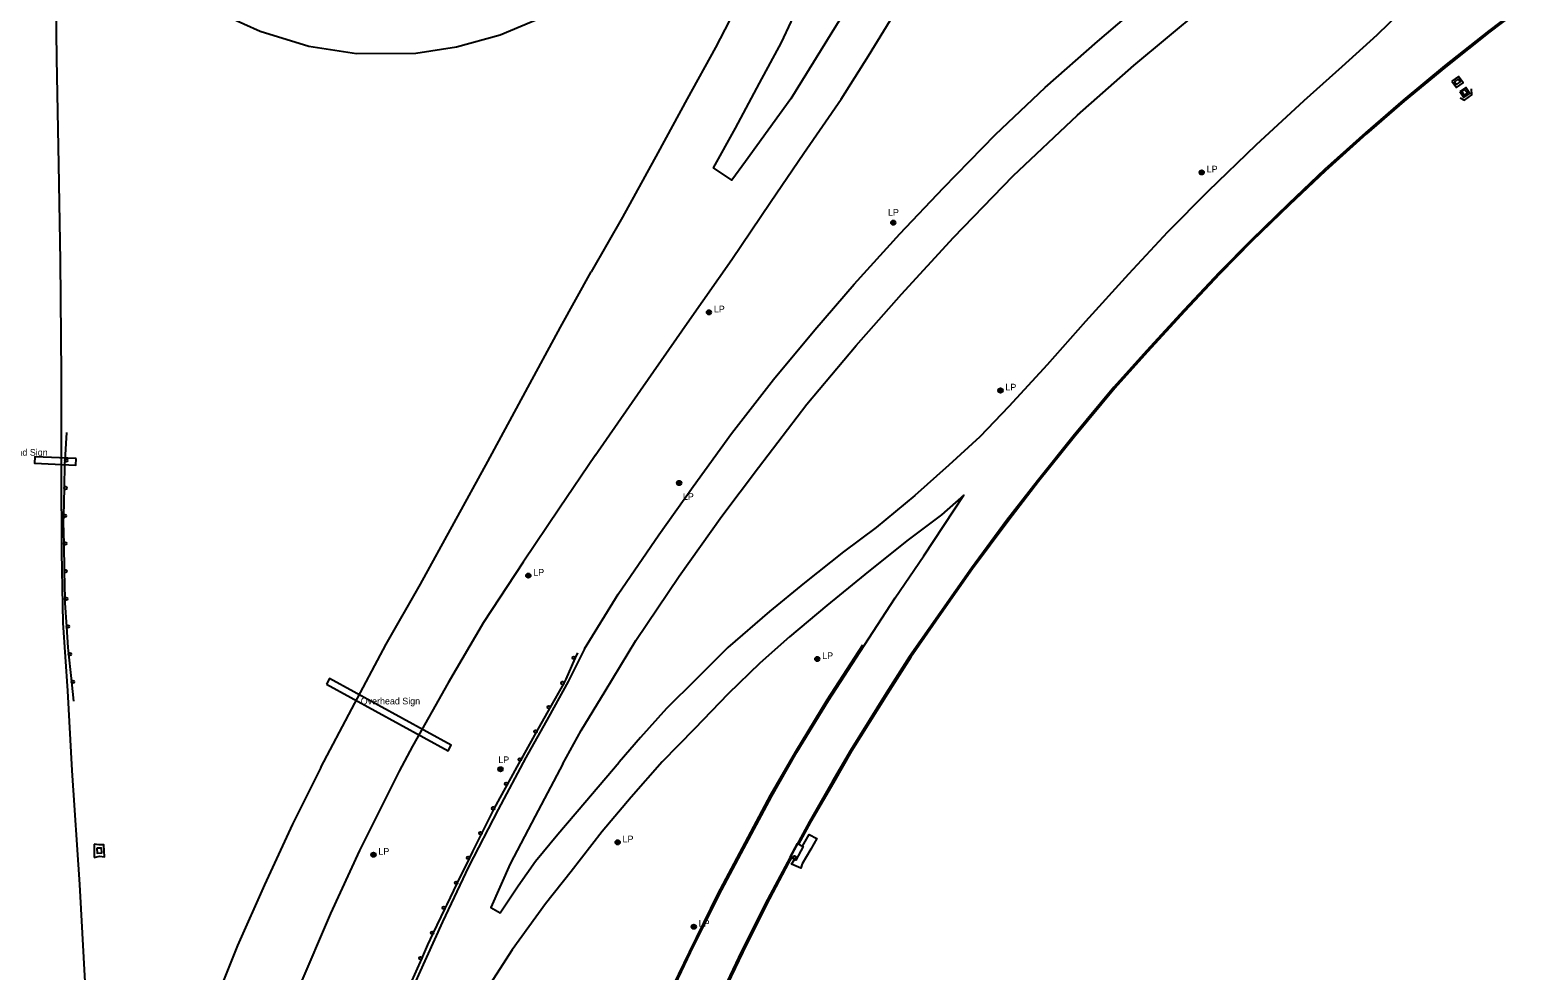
# Model space of a CAD drawing. Extents: x 2402803 to 2427059, y 6985292 to 6997652.
# Drawn here: x 2410720 to 2411807, y 6990282 to 6990960 of the extents above; entities that cross this region are included whole.
import ezdxf

# ---------------------------------------------------------------- set-up
doc = ezdxf.new("R2010")
doc.units = 0
for name, color, linetype in [('p_drainage conc drain', 7, 'Continuous'), ('p_dtm retaining wall', 7, 'Continuous'), ('p_road - paved curb', 7, 'Continuous'), ('p_road bridge end', 7, 'Continuous'), ('p_road guard rails', 7, 'Continuous'), ('p_structure general', 7, 'Continuous'), ('p_structure slab', 7, 'Continuous'), ('p_utility manhole', 7, 'Continuous')]:
    doc.layers.add(name, color=color, linetype=linetype)

msp = doc.modelspace()

# ---------------------------------------------------------------- linework, layer by layer
at = {"layer": 'p_drainage conc drain'}
for points in [[(2411276.6, 6990371.5), (2411281.4, 6990380), (2411287.1, 6990377), (2411282.8, 6990369.4), (2411276.5, 6990358.8), (2411275.4, 6990355.6), (2411268.8, 6990358.6), (2411270.8, 6990362)], [(2410766, 6990373), (2410766.1, 6990363.5)], [(2410766.1, 6990363.5), (2410770, 6990364.3), (2410773.4, 6990363.8), (2410772.9, 6990372.6), (2410769.4, 6990372.6), (2410766, 6990373)]]:
    msp.add_lwpolyline(points, dxfattribs=at)
at = {"layer": 'p_dtm retaining wall'}
msp.add_lwpolyline([(2411750.9, 6990910.7), (2411753.8, 6990909.1), (2411759.3, 6990913), (2411758.9, 6990917.3)], dxfattribs=at)
at = {"layer": 'p_road - paved curb'}
for points in [[(2411292.7, 6991404.7), (2411296.3, 6991381.2), (2411299.6, 6991355.2), (2411302.1, 6991327.9), (2411303.6, 6991291.7), (2411302.4, 6991262.3), (2411300.1, 6991232.3), (2411296.8, 6991200.2), (2411290.6, 6991161.4), (2411283.1, 6991122.4), (2411270.8, 6991077.6), (2411256.2, 6991035.2), (2411231, 6990979.9), (2411213.9, 6990947.1), (2411193.6, 6990910), (2411172.4, 6990871.2), (2411146.8, 6990824.7), (2411124.3, 6990785.3)], [(2410750.2, 6990426.2), (2410747.1, 6990483.4), (2410743.8, 6990532.5), (2410742.8, 6990583.3), (2410742.5, 6990642.4), (2410742.4, 6990711.5), (2410741.7, 6990793.4), (2410740.5, 6990862.7), (2410739.1, 6990939.1), (2410738.5, 6990996.2)], [(2411323.5, 6990999.6), (2411297.7, 6990957.8), (2411268.2, 6990910.1), (2411235.5, 6990864.8), (2411225.8, 6990851.5), (2411212.5, 6990860.3), (2411228.4, 6990888.9), (2411245.7, 6990921.3), (2411261.6, 6990950.6), (2411275.5, 6990980.3)], [(2411806.2, 6990985.6), (2411771.4, 6990959.1), (2411739.4, 6990933.7), (2411709.7, 6990909.1), (2411682.5, 6990885.5), (2411653, 6990859), (2411627.1, 6990834.4), (2411600, 6990808.1), (2411576.9, 6990784.6), (2411551.5, 6990757.8), (2411524.6, 6990728.4), (2411501, 6990702.2), (2411471.8, 6990667), (2411446, 6990634.9), (2411423.8, 6990606.1), (2411398.4, 6990571.9), (2411375.9, 6990539.7), (2411353.9, 6990508.2), (2411337.1, 6990481.9), (2411311.2, 6990440.4)], [(2411806.8, 6990984.8), (2411772.1, 6990958.3), (2411740.1, 6990932.9), (2411710.3, 6990908.3), (2411683.2, 6990884.8), (2411653.6, 6990858.2), (2411627.8, 6990833.7), (2411600.7, 6990807.4), (2411577.6, 6990783.9), (2411552.2, 6990757.1), (2411525.3, 6990727.7), (2411501.8, 6990701.6), (2411472.6, 6990666.3), (2411446.8, 6990634.3), (2411424.6, 6990605.5), (2411399.2, 6990571.3), (2411376.7, 6990539.1), (2411354.8, 6990507.7), (2411338, 6990481.4), (2411312.1, 6990439.9)], [(2411119.6, 6990513.7), (2411143.8, 6990553.1), (2411173.2, 6990596), (2411197.9, 6990630.7), (2411225.6, 6990668.9), (2411255.7, 6990707.9), (2411285.5, 6990743.6), (2411313.9, 6990776.5), (2411346.9, 6990812.8), (2411378.3, 6990846), (2411415.7, 6990884.4), (2411451.6, 6990918.1), (2411489.3, 6990951.3), (2411525.1, 6990982.2)], [(2411127.2, 6990653.1), (2411159.9, 6990700.1), (2411195.2, 6990750.9), (2411225.7, 6990794.3), (2411253.5, 6990835.7), (2411277.6, 6990871), (2411304.6, 6990909.8), (2411324.2, 6990941), (2411346.3, 6990977)], [(2411134.5, 6990483.2), (2411156.6, 6990519.8), (2411187.8, 6990566.1), (2411218.5, 6990609.4), (2411245, 6990644.3), (2411279.9, 6990690.1), (2411315.4, 6990732.4), (2411348.1, 6990769.3), (2411385.5, 6990810.2), (2411428.5, 6990854.5), (2411474.9, 6990898.2), (2411515.5, 6990934.1), (2411564.1, 6990974.5)], [(2411716.4, 6990981), (2411690.7, 6990956), (2411665.4, 6990933), (2411638, 6990908.5), (2411603.4, 6990876.7), (2411569, 6990843.6), (2411539.9, 6990814), (2411511.6, 6990783.6), (2411480.7, 6990749.6), (2411453, 6990718.4), (2411425.3, 6990688.3), (2411404.4, 6990666.6), (2411382.1, 6990646.1), (2411357.6, 6990624.2), (2411329.7, 6990601.1), (2411306.3, 6990583.6), (2411278.2, 6990561.3), (2411252.9, 6990540.6), (2411222.9, 6990514.6), (2411200.1, 6990491.8), (2411178.7, 6990470.8), (2411160, 6990449.8), (2411144.5, 6990432.2)], [(2410862.2, 6990969.3), (2410885.7, 6990958.8), (2410920.9, 6990947.9), (2410955.1, 6990942.6), (2410997.9, 6990942.9), (2411027.2, 6990947.4), (2411058.7, 6990956.2), (2411088.5, 6990968.6)], [(2410929.5, 6990428.2), (2410951.9, 6990470.5), (2410976.5, 6990517.1), (2411001.2, 6990560.4), (2411025.5, 6990604.5), (2411049.8, 6990648.7), (2411077, 6990698.9), (2411102.2, 6990745.6), (2411124.3, 6990785.3)], [(2411127.2, 6990653.1), (2411101.4, 6990615.2), (2411075.3, 6990576.3), (2411046.7, 6990532.6), (2411021.3, 6990489.3), (2410995.5, 6990443.5), (2410986, 6990425.7)], [(2411321.1, 6990516.1), (2411343.5, 6990550.4), (2411364.2, 6990580.7), (2411392.9, 6990624.4), (2411376.8, 6990610.4), (2411351.9, 6990591.5), (2411321.6, 6990567.4), (2411294.1, 6990545), (2411267.3, 6990522.5), (2411245.9, 6990503.5), (2411223.1, 6990481.4), (2411198.9, 6990456.2), (2411175.5, 6990432.4)], [(2411119.6, 6990513.7), (2411107.7, 6990490.2), (2411093.6, 6990464.5), (2411077.2, 6990435.4)], [(2411271.9, 6990439.8), (2411294.4, 6990477), (2411320.2, 6990516.7)], [(2411272.7, 6990439.3), (2411295.3, 6990476.5), (2411321.1, 6990516.1)], [(2411104, 6990431), (2411117, 6990454.8), (2411134.5, 6990483.2)], [(2411077.2, 6990435.4), (2411057.3, 6990398.1), (2411035.8, 6990356.7), (2411017.1, 6990317.1), (2410999.9, 6990278.9), (2410983.4, 6990241.6), (2410965.2, 6990196.4), (2410949.7, 6990154), (2410931.2, 6990099.7), (2410915.5, 6990049.2), (2410901.9, 6990001.9), (2410888.9, 6989953.2), (2410879.3, 6989910), (2410868.1, 6989857.3), (2410860.6, 6989809.8), (2410850.7, 6989745.5), (2410845.4, 6989691.3), (2410843.9, 6989676.2)], [(2411175.5, 6990432.4), (2411153.1, 6990406.8), (2411132.3, 6990382.1), (2411109.8, 6990353.4), (2411091.4, 6990329.9), (2411067.4, 6990296.9), (2411044.9, 6990261.8), (2411028, 6990236), (2411013.1, 6990206.7), (2410990.6, 6990163), (2410969.3, 6990114.8), (2410949.6, 6990066.5), (2410933.3, 6990021), (2410918.6, 6989972.7), (2410906.2, 6989919.8), (2410894.1, 6989861.8), (2410886.5, 6989819.5), (2410876.9, 6989763.5), (2410873, 6989734.9), (2410867.2, 6989682.7), (2410866.8, 6989677.5)], [(2411104, 6990431), (2411083.9, 6990393.1), (2411065.9, 6990358.9), (2411052, 6990327.4), (2411058.7, 6990323.5), (2411071.8, 6990343.1), (2411084.3, 6990360.8), (2411100.2, 6990380.2), (2411119.8, 6990403.1), (2411144.5, 6990432.2)], [(2411055.6, 6989902.9), (2411061.7, 6989926.2), (2411068.4, 6989953.3), (2411077.7, 6989986.1), (2411086.7, 6990017), (2411097.2, 6990050.2), (2411106.7, 6990079.9), (2411118.3, 6990111.9), (2411130.8, 6990146.1), (2411146.2, 6990184.9), (2411163.4, 6990226), (2411179.6, 6990263), (2411195.1, 6990295.3), (2411215.6, 6990337), (2411233.4, 6990370.4), (2411253.6, 6990408.2), (2411271.9, 6990439.8)], [(2411056.5, 6989902.6), (2411062.7, 6989925.9), (2411069.4, 6989953.1), (2411078.7, 6989985.8), (2411087.7, 6990016.8), (2411098.1, 6990049.9), (2411107.7, 6990079.6), (2411119.2, 6990111.6), (2411131.7, 6990145.8), (2411147.1, 6990184.5), (2411164.4, 6990225.6), (2411180.5, 6990262.5), (2411196, 6990294.9), (2411216.5, 6990336.6), (2411234.3, 6990369.9), (2411254.5, 6990407.7), (2411272.7, 6990439.3)], [(2411311.2, 6990440.4), (2411298.1, 6990417.8), (2411281.6, 6990389.3), (2411265.8, 6990360.1), (2411249.8, 6990330), (2411232.8, 6990295.8), (2411215.9, 6990260.4)], [(2411312.1, 6990439.9), (2411299, 6990417.3), (2411282.5, 6990388.9), (2411273.9, 6990373)], [(2410929.5, 6990428.2), (2410909.1, 6990387.5), (2410888.8, 6990343.6), (2410869.3, 6990300), (2410848.5, 6990247.8), (2410831.5, 6990202.2), (2410816.7, 6990156.7), (2410801.9, 6990109.4), (2410784.9, 6990050.6), (2410774.9, 6990010.3), (2410767.1, 6989980.5), (2410762.1, 6989982), (2410763.1, 6990047.1), (2410762.3, 6990116.3), (2410761.8, 6990192.5), (2410759.6, 6990273.9), (2410755.8, 6990343.9), (2410750.2, 6990426.2)], [(2410986, 6990425.7), (2410957.4, 6990368.4), (2410936.4, 6990323), (2410913.6, 6990269.7), (2410894.9, 6990223.2), (2410875, 6990171.1), (2410860, 6990123.7), (2410841.8, 6990060.8), (2410824.8, 6989993.5), (2410812.6, 6989945.6), (2410800, 6989885.2), (2410789.9, 6989823.8), (2410780.5, 6989751.8), (2410774.9, 6989685.5)], [(2411268.5, 6990363), (2411266.6, 6990359.6), (2411250.7, 6990329.5), (2411233.7, 6990295.3), (2411216.8, 6990260), (2411202.3, 6990227.4), (2411182.4, 6990181.6), (2411167, 6990142.5), (2411157.1, 6990116.7)]]:
    msp.add_lwpolyline(points, dxfattribs=at)
at = {"layer": 'p_road bridge end'}
for points in [[(2410767.9, 6990370.1), (2410768.1, 6990366.5), (2410771.5, 6990366.7), (2410771.3, 6990370.2)], [(2411267.8, 6990363.6), (2411273.1, 6990373.4), (2411277.1, 6990371.3), (2411271.8, 6990361.5)]]:
    msp.add_lwpolyline(points, close=True, dxfattribs=at)
at = {"layer": 'p_road guard rails'}
for p, q in [((2410746, 6990669.5), (2410744.8, 6990649.6)), ((2410744.3, 6990629.6), (2410743.9, 6990609.6)), ((2410744.1, 6990589.6), (2410744.5, 6990569.7)), ((2410744.5, 6990569.7), (2410744.9, 6990549.7)), ((2411112.9, 6990506.8), (2411114.6, 6990510.9)), ((2410749.6, 6990489.9), (2410751.2, 6990476.1)), ((2411094.7, 6990471.2), (2411104.5, 6990488.6)), ((2411085, 6990453.7), (2411094.7, 6990471.2)), ((2411075.2, 6990436.3), (2411085, 6990453.7)), ((2411064, 6990416), (2411073.7, 6990433.5)), ((2411073.7, 6990433.5), (2411075.2, 6990436.3)), ((2411045.5, 6990380.6), (2411054.5, 6990398.4)), ((2411027.8, 6990344.7), (2411036.5, 6990362.7)), ((2411010.5, 6990308.7), (2411019.1, 6990326.7)), ((2410994.2, 6990272.2), (2411002.2, 6990290.5))]:
    msp.add_line(p, q, dxfattribs=at)
for points in [[(2410744.8, 6990649.6), (2410744.7, 6990647.4), (2410744.3, 6990629.6)], [(2410743.9, 6990609.6), (2410743.8, 6990604.9), (2410744.1, 6990589.6)], [(2410744.9, 6990549.7), (2410745, 6990547), (2410746.1, 6990529.7)], [(2410746.1, 6990529.7), (2410747, 6990514.6), (2410747.5, 6990509.8)], [(2410747.5, 6990509.8), (2410749.1, 6990494.5), (2410749.6, 6990489.9)], [(2411104.5, 6990488.6), (2411106.4, 6990492), (2411112.9, 6990506.8)], [(2411054.5, 6990398.4), (2411057.3, 6990403.8), (2411064, 6990416)], [(2411036.5, 6990362.7), (2411039, 6990367.8), (2411045.5, 6990380.6)], [(2411019.1, 6990326.7), (2411020.5, 6990329.5), (2411027.8, 6990344.7)], [(2411002.2, 6990290.5), (2411006.6, 6990300.5), (2411010.5, 6990308.7)]]:
    msp.add_lwpolyline(points, dxfattribs=at)
for centre in [(2410745.8, 6990649.5), (2410745.3, 6990629.6), (2410744.9, 6990609.6), (2410745.1, 6990589.7), (2410745.5, 6990569.7), (2410745.9, 6990549.7), (2410747.1, 6990529.8), (2410748.5, 6990509.9), (2411111.9, 6990507.2), (2410750.6, 6990490), (2411103.6, 6990489.1), (2411093.9, 6990471.7), (2411084.1, 6990454.2), (2411072.8, 6990434), (2411063.1, 6990416.5), (2411053.6, 6990398.8), (2411044.6, 6990381), (2411035.6, 6990363.1), (2411026.9, 6990345.2), (2411018.2, 6990327.2), (2411009.6, 6990309.1), (2411001.3, 6990290.9)]:
    msp.add_circle(centre, 1, dxfattribs=at)
at = {"layer": 'p_structure general'}
for points in [[(2411746.8, 6990922.2), (2411749.5, 6990924.1), (2411750.7, 6990922.3), (2411748, 6990920.4)], [(2411752, 6990915.2), (2411754.2, 6990916.7), (2411756, 6990914.3), (2411753.7, 6990912.7)], [(2410753, 6990650.8), (2410723.2, 6990652.2), (2410723, 6990647.5), (2410752.8, 6990646.1)], [(2410933.5, 6990488.2), (2411021.2, 6990440.2), (2411023.5, 6990444.4), (2410935.7, 6990492.4)]]:
    msp.add_lwpolyline(points, close=True, dxfattribs=at)
msp.add_circle((2411271, 6990363.6), 1, dxfattribs=at)
at = {"layer": 'p_structure slab'}
for points in [[(2411744.8, 6990922.8), (2411748.2, 6990918.1), (2411752.9, 6990921.5), (2411749.5, 6990926.1)], [(2411750.5, 6990915.3), (2411753.4, 6990910.9), (2411757.7, 6990913.8), (2411754.8, 6990918.2)]]:
    msp.add_lwpolyline(points, close=True, dxfattribs=at)
at = {"layer": 'p_utility manhole'}
for centre, radius in [((2411564.5, 6990857), 1.6), ((2411564.5, 6990857), 1.3), ((2411564.5, 6990857), 1), ((2411564.5, 6990857), 0.539), ((2411564.5, 6990857), 0.192), ((2411342.1, 6990820.8), 1.6), ((2411342.1, 6990820.8), 1.3), ((2411342.1, 6990820.8), 1), ((2411342.1, 6990820.8), 0.539), ((2411342.1, 6990820.8), 0.192), ((2411209.2, 6990756.2), 1.6), ((2411209.2, 6990756.2), 1.3), ((2411209.2, 6990756.2), 1), ((2411209.2, 6990756.2), 0.539), ((2411209.2, 6990756.2), 0.192), ((2411419.4, 6990699.9), 1.6), ((2411419.4, 6990699.9), 1.3), ((2411419.4, 6990699.9), 1), ((2411419.4, 6990699.9), 0.539), ((2411419.4, 6990699.9), 0.192), ((2411187.8, 6990633.2), 1.6), ((2411187.8, 6990633.2), 1.3), ((2411187.8, 6990633.2), 1), ((2411187.8, 6990633.2), 0.539), ((2411187.8, 6990633.2), 0.192), ((2411079, 6990566.5), 1.6), ((2411079, 6990566.5), 1.3), ((2411079, 6990566.5), 1), ((2411079, 6990566.5), 0.539), ((2411079, 6990566.5), 0.192), ((2411287.3, 6990506.4), 1.6), ((2411287.3, 6990506.4), 1.3), ((2411287.3, 6990506.4), 1), ((2411287.3, 6990506.4), 0.539), ((2411287.3, 6990506.4), 0.192), ((2411059, 6990427), 1.6), ((2411059, 6990427), 1.3), ((2411059, 6990427), 1), ((2411059, 6990427), 0.539), ((2411059, 6990427), 0.192), ((2411143.4, 6990374.3), 1.6), ((2410967.4, 6990365.4), 1.6), ((2410967.4, 6990365.4), 1.3), ((2410967.4, 6990365.4), 1), ((2410967.4, 6990365.4), 0.539), ((2410967.4, 6990365.4), 0.192), ((2411143.4, 6990374.3), 1.3), ((2411143.4, 6990374.3), 1), ((2411143.4, 6990374.3), 0.539), ((2411143.4, 6990374.3), 0.192), ((2411198.3, 6990313.5), 1.6), ((2411198.3, 6990313.5), 1.3), ((2411198.3, 6990313.5), 1), ((2411198.3, 6990313.5), 0.539), ((2411198.3, 6990313.5), 0.192)]:
    msp.add_circle(centre, radius, dxfattribs=at)

# ---------------------------------------------------------------- texts
at = {"layer": 'p_structure general'}
for p in [(2410689.7, 6990652.9), (2410958.2, 6990473.7)]:
    msp.add_text('Overhead Sign', height=4.8, dxfattribs=at).set_placement(p)
at = {"layer": 'p_utility manhole'}
for p in [(2411564.5, 6990857), (2411334.7, 6990825.8), (2411209.2, 6990756.2), (2411419.4, 6990699.9), (2411186.9, 6990621.1), (2411079, 6990566.5), (2411287.3, 6990506.4), (2411053.8, 6990431.4), (2411143.4, 6990374.3), (2410967.4, 6990365.4), (2411198.3, 6990313.5)]:
    msp.add_text('  LP', height=4.8, dxfattribs=at).set_placement(p)

doc.saveas('drawing.dxf')
